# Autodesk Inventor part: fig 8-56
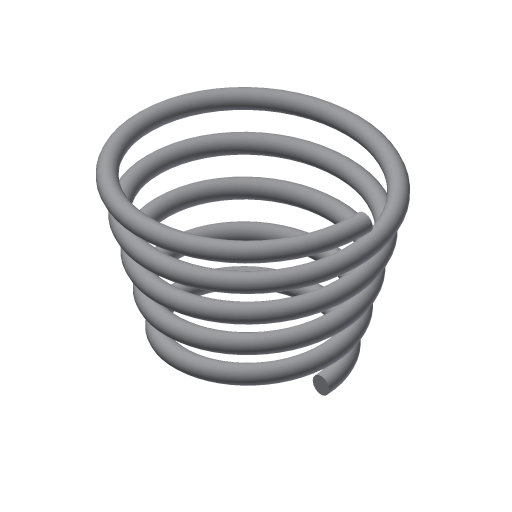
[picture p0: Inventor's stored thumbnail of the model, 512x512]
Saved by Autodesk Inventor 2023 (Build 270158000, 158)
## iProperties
Created: 2002-01
Part Number: fig 8-56
Document SubType Name: Modeling
Designer: CADSoft
Density: 1 g/cm^3
Material: Generic
Appearance: Default
Control State: 0
Master: False
Checked Out: False
Shininess: 77.0
Length Units: 11269
Angle Units: 11279
Time Units: 11290
Mass Units: 11283
Length Display Precision: 3
Angle Display Precision: 2
Density: 0.0
Volumn: 0.0
Area: 0.0
PropertySet Name: Model Information
Author: CADSoft
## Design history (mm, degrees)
sketch "Sketch2"
  geometry: C1 r 2.5 at (-19.895, -0.092)
  constraints: 1 centre point
  dimensions: "d0" = 5 diameter of C1
coil "Coil5" sketch "Sketch2" pitch "d35" = 10; turns "d37" = 5; dims "d36" = 10, "d38" = 15 deg, angle "d39" = 90 deg, angle "d40" = 90 deg, "d41" = 0, "d42" = 0
body "Solid1"
